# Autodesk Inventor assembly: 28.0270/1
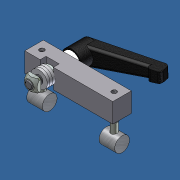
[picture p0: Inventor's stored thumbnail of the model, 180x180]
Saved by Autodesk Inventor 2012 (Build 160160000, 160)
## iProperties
Created: 2007-06
Part Number: 28.0270/1
Document SubType Name: Assembly
Designer: Andy Moles
Description: SLIDE CLAMPING UNIT FOR SLIDE LWN-S
Author: Andy Moles
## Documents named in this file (9)
- C:\Andys Backup Data\ANDY'S INVENTOR\INVENTOR LIBRARIES\PARTS LIBRARY\COMPONENTS LR\28.0270_1 SLIDE CLAMPING UNIT FOR SLIDE LWN-S.iam
- C:\Andys Backup Data\ANDY'S INVENTOR\INVENTOR LIBRARIES\PARTS LIBRARY\FASTENING ELEMENTS\WASHERS\WASHER M8 PLASTIC 17mm OD.ipt
- C:\Andys Backup Data\ANDY'S INVENTOR\INVENTOR LIBRARIES\PARTS LIBRARY\COMPONENTS LR\SUBCOMPONENTS\28.0270 SLIDE CLAMPING UNIT HANDLE.ipt
- C:\Andys Backup Data\ANDY'S INVENTOR\INVENTOR LIBRARIES\PARTS LIBRARY\COMPONENTS LR\SUBCOMPONENTS\28.0270 THREADED STUD.ipt
- C:\Andys Backup Data\ANDY'S INVENTOR\INVENTOR LIBRARIES\PARTS LIBRARY\FASTENING ELEMENTS\NUTS\21.1351 M8 SQUARE NUT.ipt
- C:\Andys Backup Data\ANDY'S INVENTOR\INVENTOR LIBRARIES\PARTS LIBRARY\FASTENING ELEMENTS\SET SCREWS\21.9841 M4X5 FLAT POINT DIN 913.ipt
- C:\Andys Backup Data\ANDY'S INVENTOR\INVENTOR LIBRARIES\PARTS LIBRARY\COMPONENTS LR\SUBCOMPONENTS\28.0270_1 SLIDE CLAMPING AL BLOCK FOR SLIDE LWN-S.ipt
- C:\Andys Backup Data\ANDY'S INVENTOR\INVENTOR LIBRARIES\PARTS LIBRARY\FASTENING ELEMENTS\SUBCOMPONENTS\21.1024 BOLT FASTENER 15.ipt
- C:\Andys Backup Data\ANDY'S INVENTOR\INVENTOR LIBRARIES\PARTS LIBRARY\FASTENING ELEMENTS\SCREWS CAP\21.1245 M6X35.ipt
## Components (13 placed, 8 different names)
1. 28.0270_1 SLIDE CLAMPING AL BLOCK FOR SLIDE LWN-S:1 — Angle:2, Insert:12, Angle:3, Flush:1, Flush:2, Mate:8, Mate:9, Flush:3, Flush:4, Mate:10
2. WASHER M8 PLASTIC 17mm OD:1 — Insert:13, Insert:14
3. WASHER M8 PLASTIC 17mm OD:3 — Insert:15, Flush:1, Mate:7
4. 28.0270 SLIDE CLAMPING UNIT HANDLE:1 — Mate:4, Insert:11, Insert:12, Mate:11
5. 28.0270 THREADED STUD:1 — Insert:11, Mate:5, Mate:6
6. 21.1351 M8 SQUARE NUT:1 — Mate:5, Angle:3, Insert:13
7. 21.1351 M8 SQUARE NUT:2 — Angle:2, Mate:6, Mate:7
8. 21.9841 SET SCREW M4X5 FLAT POINT DIN 913:1 — Mate:4, Mate:11
9. WASHER M8 PLASTIC 17mm OD:4 — Insert:14, Insert:15
10. 21.1024 BOLT FASTENER 15:1 — Flush:2, Mate:8, Mate:9, Insert:17
11. 21.1024 BOLT FASTENER 15:2 — Flush:3, Flush:4, Mate:10, Insert:16
12. 21.1245  M6 x 35:1 — Insert:16
13. 21.1245  M6 x 35:2 — Insert:17
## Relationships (21: Mate 8, Insert 7, Flush 4, Angle 2)
- Mate:4: 28.0270 SLIDE CLAMPING UNIT HANDLE:1 ↔ 21.9841 SET SCREW M4X5 FLAT POINT DIN 913:1
- Insert:11: 28.0270 SLIDE CLAMPING UNIT HANDLE:1 ↔ 28.0270 THREADED STUD:1
- Angle:2: 28.0270_1 SLIDE CLAMPING AL BLOCK FOR SLIDE LWN-S:1 ↔ 21.1351 M8 SQUARE NUT:2
- Insert:12: 28.0270_1 SLIDE CLAMPING AL BLOCK FOR SLIDE LWN-S:1 ↔ 28.0270 SLIDE CLAMPING UNIT HANDLE:1
- Mate:5: 28.0270 THREADED STUD:1 ↔ 21.1351 M8 SQUARE NUT:1
- Angle:3: 28.0270_1 SLIDE CLAMPING AL BLOCK FOR SLIDE LWN-S:1 ↔ 21.1351 M8 SQUARE NUT:1
- Insert:13: WASHER M8 PLASTIC 17mm OD:1 ↔ 21.1351 M8 SQUARE NUT:1
- Insert:14: WASHER M8 PLASTIC 17mm OD:1 ↔ WASHER M8 PLASTIC 17mm OD:4
- Insert:15: WASHER M8 PLASTIC 17mm OD:3 ↔ WASHER M8 PLASTIC 17mm OD:4
- Mate:6: 28.0270 THREADED STUD:1 ↔ 21.1351 M8 SQUARE NUT:2
- Flush:1: 28.0270_1 SLIDE CLAMPING AL BLOCK FOR SLIDE LWN-S:1 ↔ WASHER M8 PLASTIC 17mm OD:3
- Mate:7: WASHER M8 PLASTIC 17mm OD:3 ↔ 21.1351 M8 SQUARE NUT:2
- Flush:2: 28.0270_1 SLIDE CLAMPING AL BLOCK FOR SLIDE LWN-S:1 ↔ 21.1024 BOLT FASTENER 15:1
- Mate:8: 28.0270_1 SLIDE CLAMPING AL BLOCK FOR SLIDE LWN-S:1 ↔ 21.1024 BOLT FASTENER 15:1
- Mate:9: 28.0270_1 SLIDE CLAMPING AL BLOCK FOR SLIDE LWN-S:1 ↔ 21.1024 BOLT FASTENER 15:1
- Flush:3: 28.0270_1 SLIDE CLAMPING AL BLOCK FOR SLIDE LWN-S:1 ↔ 21.1024 BOLT FASTENER 15:2
- Flush:4: 28.0270_1 SLIDE CLAMPING AL BLOCK FOR SLIDE LWN-S:1 ↔ 21.1024 BOLT FASTENER 15:2
- Mate:10: 28.0270_1 SLIDE CLAMPING AL BLOCK FOR SLIDE LWN-S:1 ↔ 21.1024 BOLT FASTENER 15:2
- Insert:16: 21.1024 BOLT FASTENER 15:2 ↔ 21.1245  M6 x 35:1
- Insert:17: 21.1024 BOLT FASTENER 15:1 ↔ 21.1245  M6 x 35:2
- Mate:11: 28.0270 SLIDE CLAMPING UNIT HANDLE:1 ↔ 21.9841 SET SCREW M4X5 FLAT POINT DIN 913:1
